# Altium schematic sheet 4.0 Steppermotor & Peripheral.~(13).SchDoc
size A4; SheetNumber: 4; SheetTotal: 7
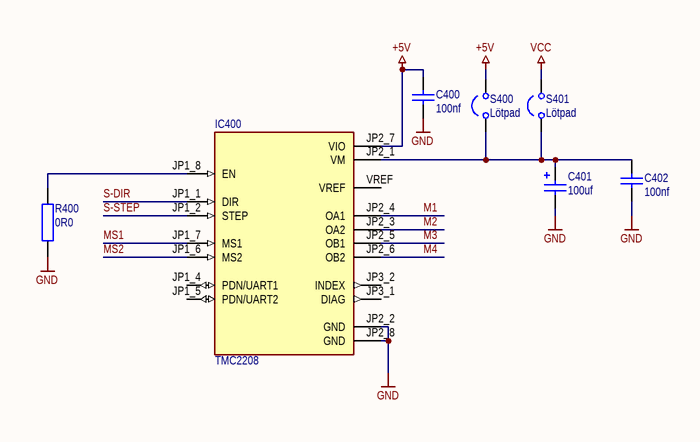
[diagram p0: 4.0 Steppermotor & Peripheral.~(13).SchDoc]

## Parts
C400  100nf  [C_SMD_0805]
C401  100uf  [C_SMD_D-TYP]
C402  100nf  [C_SMD_0805]
IC400  TMC2208  [IC_TMC2208]
R400  0R0  [R_SMD_0805]
S400  Lötpad  [S_SMD_Pad-NC]
S401  Lötpad  [S_SMD_Pad-NO]

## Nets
+5V: C400.1 IC400.JP2_7(VIO) S400.2
GND: C400.2 C401.2 C402.2 IC400.JP2_2(GND) IC400.JP2_8(GND) R400.1
VCC: S401.2
M1: IC400.JP2_4(OA1)
M2: IC400.JP2_3(OA2)
M3: IC400.JP2_5(OB1)
M4: IC400.JP2_6(OB2)
MS1: IC400.JP1_7(MS1)
MS2: IC400.JP1_6(MS2)
S-DIR: IC400.JP1_1(DIR)
S-STEP: IC400.JP1_2(STEP)
NetC401_1: C401.1 C402.1 IC400.JP2_1(VM) S400.1 S401.1
NetIC400_JP1_8: IC400.JP1_8(EN) R400.2

Not connected (* = marked no-connect by the designer): IC400 JP1_4(PDN/UART1) JP1_5(PDN/UART2) JP3_1(DIAG) JP3_2(INDEX) VREF

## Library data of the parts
C400 C402 = C_SMD_KO: Kondensator SMD Universal, Keramik, Folie, usw.
C401 = C_SMD_ELK: SMD Elektrolytkondensator
IC400 = IC_TMC2208: Schrittmotortreiber
R400 = R_SMD_Widerstand: Widerstand SMD
S400 S401 = S_SMD_Jumper: Lötverbinder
